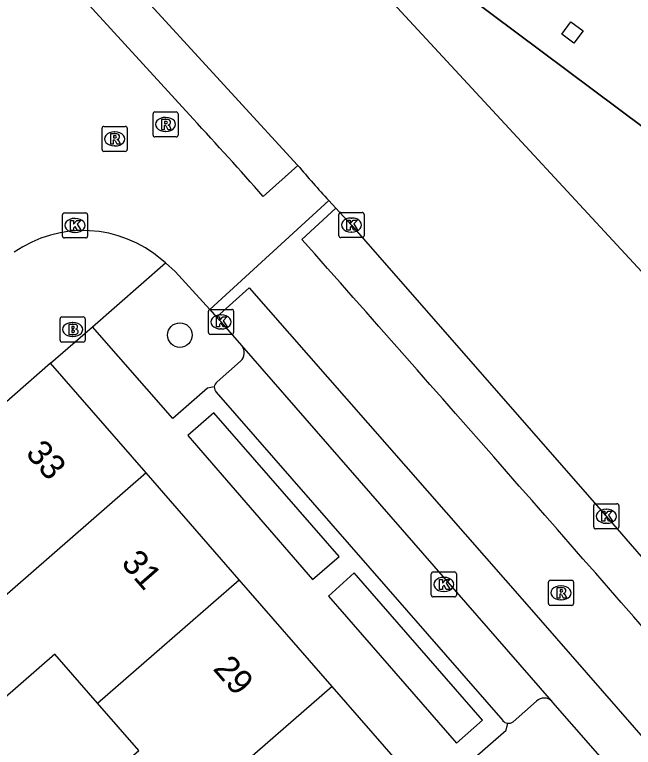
# Model space of a CAD drawing. Extents: x 159718 to 160783, y 383290 to 384030.
# Drawn here: x 160469.71 to 160494.4, y 383567.02 to 383596.25 of the extents above; entities that cross this region are included whole.
import ezdxf

# ---------------------------------------------------------------- set-up
doc = ezdxf.new("R2010")
doc.units = 0
for name, color, linetype in [('IMGEO_Boom', 7, 'Continuous'), ('IMGEO_Brandkraan', 7, 'Continuous'), ('IMGEO_Kolk', 7, 'Continuous'), ('IMGEO_Pand', 7, 'Continuous'), ('IMGEO_Pand_nummerreeks', 7, 'Continuous'), ('IMGEO_Pand_overbouw', 7, 'Continuous'), ('IMGEO_Parkeervlak_open', 7, 'Continuous'), ('IMGEO_Rijbaan_lokaal_gesloten', 7, 'Continuous'), ('IMGEO_Rijbaan_lokaal_open', 7, 'Continuous'), ('IMGEO_Rioolput', 7, 'Continuous'), ('IMGEO_Voetpad_open', 7, 'Continuous')]:
    doc.layers.add(name, color=color, linetype=linetype)

msp = doc.modelspace()

# ---------------------------------------------------------------- linework, layer by layer
at = {"layer": 'IMGEO_Boom'}
msp.add_circle((160476.304, 383583.468), 0.489, dxfattribs=at)
at = {"layer": 'IMGEO_Brandkraan'}
for p, q in [((160471.525, 383583.266), (160471.525, 383584.118)), ((160471.6, 383584.192), (160472.452, 383584.192)), ((160472.526, 383584.118), (160472.526, 383583.266)), ((160472.013, 383583.972), (160472.038, 383583.972)), ((160472.452, 383583.192), (160471.6, 383583.192)), ((160472.036, 383583.412), (160472.011, 383583.412))]:
    msp.add_line(p, q, dxfattribs=at)
for points in [[(160471.525, 383583.266), (160471.525, 383584.118)], [(160471.6, 383584.192), (160472.452, 383584.192)], [(160472.526, 383584.118), (160472.526, 383583.266)], [(160471.873, 383583.892), (160471.873, 383583.492), (160472.086, 383583.492)], [(160472.104, 383583.892), (160471.873, 383583.892)], [(160472.052, 383583.811), (160471.998, 383583.811), (160471.998, 383583.735)], [(160471.998, 383583.735), (160472.051, 383583.735)], [(160472.06, 383583.659), (160471.998, 383583.659), (160471.998, 383583.578)], [(160471.998, 383583.578), (160472.06, 383583.578)], [(160472.452, 383583.192), (160471.6, 383583.192)]]:
    msp.add_lwpolyline(points, dxfattribs=at)
for centre, radius, start, end in [((160471.602, 383584.116), 0.0765, 91.552, 178.448), ((160471.602, 383584.116), 0.0765, 91.552, 178.448), ((160472.45, 383584.116), 0.0765, 1.552, 88.448), ((160472.45, 383584.116), 0.0765, 1.552, 88.448), ((160472.053, 383583.773), 0.0379, 267.8285, 90.9355), ((160472.108, 383583.747), 0.145, 59.4692, 91.5367), ((160472.133, 383583.794), 0.0922, 285.5137, 58.1501), ((160472.061, 383583.618), 0.0404, 269.8759, 90.5077), ((160472.092, 383583.743), 0.251, 268.6676, 293.5347), ((160472.138, 383583.602), 0.105, 301.3115, 78.989), ((160471.602, 383583.268), 0.0765, 181.552, 268.448), ((160471.602, 383583.268), 0.0765, 181.552, 268.448), ((160472.45, 383583.268), 0.0765, 271.552, 358.448), ((160472.45, 383583.268), 0.0765, 271.552, 358.448)]:
    msp.add_arc(centre, radius, start, end, dxfattribs=at)
for centre, major_axis, ratio, start_param, end_param in [((160472.012, 383583.692), (-0.387, 0.002), 0.722429, 4.712389, 7.853982), ((160472.037, 383583.692), (-0.39, 0.002), 0.717154, 1.570796, 4.712389)]:
    msp.add_ellipse(centre, major_axis=major_axis, ratio=ratio, start_param=start_param, end_param=end_param, dxfattribs=at)
at = {"layer": 'IMGEO_Kolk'}
for p, q in [((160471.622, 383587.416), (160471.622, 383588.268)), ((160471.697, 383588.342), (160472.549, 383588.342)), ((160472.623, 383588.268), (160472.623, 383587.416)), ((160482.65, 383587.432), (160482.65, 383588.284)), ((160482.725, 383588.358), (160483.577, 383588.358)), ((160483.651, 383588.284), (160483.651, 383587.432)), ((160472.11, 383588.122), (160472.135, 383588.122)), ((160483.138, 383588.138), (160483.163, 383588.138)), ((160472.133, 383587.562), (160472.108, 383587.562)), ((160483.161, 383587.578), (160483.136, 383587.578)), ((160472.549, 383587.342), (160471.697, 383587.342)), ((160483.577, 383587.358), (160482.725, 383587.358)), ((160477.446, 383583.568), (160477.446, 383584.42)), ((160477.521, 383584.494), (160478.373, 383584.494)), ((160478.447, 383584.42), (160478.447, 383583.568)), ((160477.934, 383584.274), (160477.959, 383584.274)), ((160478.373, 383583.494), (160477.521, 383583.494)), ((160477.957, 383583.714), (160477.932, 383583.714)), ((160492.817, 383575.815), (160492.817, 383576.667)), ((160492.892, 383576.741), (160493.744, 383576.741)), ((160493.305, 383576.521), (160493.33, 383576.521)), ((160493.818, 383576.667), (160493.818, 383575.815)), ((160493.328, 383575.961), (160493.303, 383575.961)), ((160493.744, 383575.741), (160492.892, 383575.741)), ((160486.337, 383573.098), (160486.337, 383573.95)), ((160486.412, 383574.024), (160487.264, 383574.024)), ((160487.338, 383573.95), (160487.338, 383573.098)), ((160486.825, 383573.804), (160486.85, 383573.804)), ((160486.848, 383573.244), (160486.823, 383573.244)), ((160487.264, 383573.024), (160486.412, 383573.024))]:
    msp.add_line(p, q, dxfattribs=at)
for points in [[(160471.622, 383587.416), (160471.622, 383588.268)], [(160471.697, 383588.342), (160472.549, 383588.342)], [(160472.623, 383588.268), (160472.623, 383587.416)], [(160482.65, 383587.432), (160482.65, 383588.284)], [(160482.725, 383588.358), (160483.577, 383588.358)], [(160483.651, 383588.284), (160483.651, 383587.432)], [(160471.943, 383588.042), (160472.066, 383588.042), (160472.066, 383587.891), (160472.196, 383588.042), (160472.36, 383588.042), (160472.214, 383587.891), (160472.367, 383587.642), (160472.215, 383587.642), (160472.13, 383587.806), (160472.066, 383587.739), (160472.066, 383587.642), (160471.943, 383587.642), (160471.943, 383588.042)], [(160482.971, 383588.058), (160483.094, 383588.058), (160483.094, 383587.907), (160483.224, 383588.058), (160483.388, 383588.058), (160483.242, 383587.907), (160483.395, 383587.658), (160483.243, 383587.658), (160483.158, 383587.822), (160483.094, 383587.755), (160483.094, 383587.658), (160482.971, 383587.658), (160482.971, 383588.058)], [(160472.549, 383587.342), (160471.697, 383587.342)], [(160483.577, 383587.358), (160482.725, 383587.358)], [(160477.446, 383583.568), (160477.446, 383584.42)], [(160477.521, 383584.494), (160478.373, 383584.494)], [(160478.447, 383584.42), (160478.447, 383583.568)], [(160477.767, 383584.194), (160477.89, 383584.194), (160477.89, 383584.043), (160478.02, 383584.194), (160478.184, 383584.194), (160478.038, 383584.043), (160478.191, 383583.794), (160478.039, 383583.794), (160477.954, 383583.958), (160477.89, 383583.891), (160477.89, 383583.794), (160477.767, 383583.794), (160477.767, 383584.194)], [(160478.373, 383583.494), (160477.521, 383583.494)], [(160492.817, 383575.815), (160492.817, 383576.667)], [(160492.892, 383576.741), (160493.744, 383576.741)], [(160493.818, 383576.667), (160493.818, 383575.815)], [(160493.138, 383576.441), (160493.261, 383576.441), (160493.261, 383576.29), (160493.391, 383576.441), (160493.555, 383576.441), (160493.409, 383576.29), (160493.562, 383576.041), (160493.41, 383576.041), (160493.325, 383576.205), (160493.261, 383576.138), (160493.261, 383576.041), (160493.138, 383576.041), (160493.138, 383576.441)], [(160493.744, 383575.741), (160492.892, 383575.741)], [(160486.337, 383573.098), (160486.337, 383573.95)], [(160486.412, 383574.024), (160487.264, 383574.024)], [(160487.338, 383573.95), (160487.338, 383573.098)], [(160486.658, 383573.724), (160486.781, 383573.724), (160486.781, 383573.573), (160486.911, 383573.724), (160487.075, 383573.724), (160486.929, 383573.573), (160487.082, 383573.324), (160486.93, 383573.324), (160486.845, 383573.488), (160486.781, 383573.421), (160486.781, 383573.324), (160486.658, 383573.324), (160486.658, 383573.724)], [(160487.264, 383573.024), (160486.412, 383573.024)]]:
    msp.add_lwpolyline(points, dxfattribs=at)
for centre, start, end in [((160471.699, 383588.266), 91.552, 178.448), ((160471.699, 383588.266), 91.552, 178.448), ((160472.547, 383588.266), 1.552, 88.448), ((160472.547, 383588.266), 1.552, 88.448), ((160482.727, 383588.282), 91.552, 178.448), ((160482.727, 383588.282), 91.552, 178.448), ((160483.575, 383588.282), 1.552, 88.448), ((160483.575, 383588.282), 1.552, 88.448), ((160471.699, 383587.418), 181.552, 268.448), ((160471.699, 383587.418), 181.552, 268.448), ((160472.547, 383587.418), 271.552, 358.448), ((160472.547, 383587.418), 271.552, 358.448), ((160482.727, 383587.434), 181.552, 268.448), ((160482.727, 383587.434), 181.552, 268.448), ((160483.575, 383587.434), 271.552, 358.448), ((160483.575, 383587.434), 271.552, 358.448), ((160477.523, 383584.418), 91.552, 178.448), ((160477.523, 383584.418), 91.552, 178.448), ((160478.371, 383584.418), 1.552, 88.448), ((160478.371, 383584.418), 1.552, 88.448), ((160477.523, 383583.57), 181.552, 268.448), ((160477.523, 383583.57), 181.552, 268.448), ((160478.371, 383583.57), 271.552, 358.448), ((160478.371, 383583.57), 271.552, 358.448), ((160492.894, 383576.665), 91.552, 178.448), ((160492.894, 383576.665), 91.552, 178.448), ((160493.742, 383576.665), 1.552, 88.448), ((160493.742, 383576.665), 1.552, 88.448), ((160492.894, 383575.817), 181.552, 268.448), ((160492.894, 383575.817), 181.552, 268.448), ((160493.742, 383575.817), 271.552, 358.448), ((160493.742, 383575.817), 271.552, 358.448), ((160486.414, 383573.948), 91.552, 178.448), ((160486.414, 383573.948), 91.552, 178.448), ((160487.262, 383573.948), 1.552, 88.448), ((160487.262, 383573.948), 1.552, 88.448), ((160486.414, 383573.1), 181.552, 268.448), ((160486.414, 383573.1), 181.552, 268.448), ((160487.262, 383573.1), 271.552, 358.448), ((160487.262, 383573.1), 271.552, 358.448)]:
    msp.add_arc(centre, 0.0765, start, end, dxfattribs=at)
for centre, major_axis, ratio, start_param, end_param in [((160472.109, 383587.842), (-0.387, 0.002), 0.722429, 4.712389, 7.853982), ((160472.134, 383587.842), (-0.39, 0.002), 0.717154, 1.570796, 4.712389), ((160483.137, 383587.858), (-0.387, 0.002), 0.722429, 4.712389, 7.853982), ((160483.162, 383587.858), (-0.39, 0.002), 0.717154, 1.570796, 4.712389), ((160477.933, 383583.994), (-0.387, 0.002), 0.722429, 4.712389, 7.853982), ((160477.958, 383583.994), (-0.39, 0.002), 0.717154, 1.570796, 4.712389), ((160493.304, 383576.241), (-0.387, 0.002), 0.722429, 4.712389, 7.853982), ((160493.329, 383576.241), (-0.39, 0.002), 0.717154, 1.570796, 4.712389), ((160486.824, 383573.524), (-0.387, 0.002), 0.722429, 4.712389, 7.853982), ((160486.849, 383573.524), (-0.39, 0.002), 0.717154, 1.570796, 4.712389)]:
    msp.add_ellipse(centre, major_axis=major_axis, ratio=ratio, start_param=start_param, end_param=end_param, dxfattribs=at)
at = {"layer": 'IMGEO_Pand'}
for points in [[(160492.027, 383595.119), (160491.545, 383595.478), (160491.906, 383595.962), (160492.388, 383595.603), (160492.027, 383595.119)], [(160471.15, 383582.344), (160465.436, 383577.354)], [(160474.958, 383577.974), (160471.15, 383582.344)], [(160474.958, 383577.974), (160464.383, 383568.766)], [(160478.672, 383573.711), (160474.958, 383577.974)], [(160473.02, 383568.79), (160478.672, 383573.711)], [(160482.386, 383569.449), (160478.672, 383573.711)], [(160473.02, 383568.79), (160471.319, 383570.744), (160466.394, 383566.457), (160465.817, 383567.119), (160464.383, 383568.766)], [(160482.386, 383569.449), (160471.801, 383560.232)], [(160486.1, 383565.186), (160482.386, 383569.449)], [(160471.801, 383560.232), (160469.735, 383562.605), (160474.667, 383566.899), (160473.02, 383568.79)]]:
    msp.add_lwpolyline(points, dxfattribs=at)
at = {"layer": 'IMGEO_Pand_overbouw'}
msp.add_lwpolyline([(160495.917, 383597.511), (160494.524, 383597.305), (160494.162, 383596.825), (160485.454, 383603.334), (160487.673, 383606.423), (160484.166, 383609.039), (160482.89, 383607.324), (160483.214, 383605.19), (160484.788, 383603.997), (160482.562, 383600.899), (160499.95, 383587.91), (160506.865, 383582.745), (160509.059, 383585.69), (160505.713, 383588.193), (160502.755, 383590.402), (160499.96, 383592.491), (160499.769, 383592.634), (160500.15, 383593.098), (160500, 383594.241), (160499.967, 383594.493)], close=True, dxfattribs=at)
at = {"layer": 'IMGEO_Parkeervlak_open'}
for points in [[(160478.73, 383582.425), (160477.792, 383581.6)], [(160489.596, 383568.037), (160490.539, 383568.866)]]:
    msp.add_lwpolyline(points, dxfattribs=at)
for centre, radius, start, end in [((160478.408, 383582.761), 0.465, 313.8084, 38.3076), ((160477.945, 383581.38), 0.268, 124.9117, 175.9676), ((160490.84, 383568.571), 0.421, 43.8069, 135.6249), ((160489.422, 383568.291), 0.308, 263.3212, 304.4943)]:
    msp.add_arc(centre, radius, start, end, dxfattribs=at)
at = {"layer": 'IMGEO_Rijbaan_lokaal_gesloten'}
for points in [[(160465.403, 383607.286), (160464.052, 383606.061), (160476.835, 383592.097)], [(160465.403, 383607.286), (160472.595, 383599.429), (160473.686, 383598.238), (160480.986, 383590.263), (160481.009, 383590.237)], [(160479.625, 383588.999), (160481.009, 383590.237)], [(160481.177, 383587.285), (160482.526, 383588.525)], [(160482.526, 383588.525), (160483.151, 383587.858), (160493.318, 383576.241), (160507.09, 383560.37), (160517.403, 383548.451), (160520.715, 383544.684), (160521.52, 383543.759), (160535.801, 383527.329), (160536.623, 383526.415), (160539.338, 383523.165), (160540.32, 383521.963), (160544.286, 383517.022), (160545.265, 383515.781), (160546.841, 383513.764), (160554.904, 383502.868), (160555.82, 383501.543), (160555.982, 383501.307), (160556.128, 383501.1)], [(160477.772, 383584.186), (160479.071, 383585.36), (160490.051, 383572.83), (160501.265, 383559.983), (160524.739, 383532.986), (160523.405, 383531.808)], [(160478.773, 383583.049), (160477.947, 383583.994), (160477.772, 383584.186)], [(160491.144, 383568.863), (160478.773, 383583.049)], [(160493.877, 383565.712), (160493.826, 383565.795), (160491.187, 383568.81), (160491.144, 383568.863)]]:
    msp.add_lwpolyline(points, dxfattribs=at)
for centre, radius, start, end in [((160354.196, 383478.846), 166.931, 41.29009, 42.7211), ((158291.054, 381648.545), 2924.953, 41.032441, 41.515876)]:
    msp.add_arc(centre, radius, start, end, dxfattribs=at)
at = {"layer": 'IMGEO_Rijbaan_lokaal_open'}
for points in [[(160506.865, 383582.745), (160499.95, 383587.91), (160482.562, 383600.899), (160484.788, 383603.997), (160483.214, 383605.19), (160482.89, 383607.324), (160484.166, 383609.039)], [(160481.663, 383600.119), (160500.034, 383580.268), (160503.013, 383576.856), (160502.786, 383576.666), (160504.559, 383574.613), (160504.469, 383574.53), (160505.419, 383573.386), (160505.313, 383573.28), (160506.11, 383572.358), (160505.892, 383572.187), (160507.269, 383570.583), (160507.15, 383570.491), (160507.725, 383569.807), (160507.406, 383569.519), (160507.804, 383569.072), (160507.126, 383568.466), (160507.308, 383568.232), (160507.099, 383568.061), (160508.276, 383566.695), (160508.753, 383566.325), (160511.866, 383562.752)], [(160482.245, 383588.832), (160477.499, 383584.485)], [(160482.526, 383588.525), (160482.245, 383588.832)], [(160475.727, 383586.349), (160475.591, 383586.469)], [(160477.499, 383584.485), (160476.119, 383586.001), (160475.727, 383586.349)], [(160477.499, 383584.485), (160477.772, 383584.186)]]:
    msp.add_lwpolyline(points, dxfattribs=at)
for centre, radius, start, end in [((160523.618, 383626.475), 55.935, 220.3801, 222.297), ((160472.446, 383582.832), 4.808, 49.1527, 124.9472)]:
    msp.add_arc(centre, radius, start, end, dxfattribs=at)
at = {"layer": 'IMGEO_Rioolput'}
for p, q in [((160475.234, 383591.445), (160475.234, 383592.297)), ((160475.309, 383592.371), (160476.161, 383592.371)), ((160476.235, 383592.297), (160476.235, 383591.445)), ((160475.722, 383592.151), (160475.747, 383592.151)), ((160473.201, 383590.868), (160473.201, 383591.72)), ((160473.276, 383591.794), (160474.128, 383591.794)), ((160474.202, 383591.72), (160474.202, 383590.868)), ((160473.689, 383591.574), (160473.714, 383591.574)), ((160476.161, 383591.371), (160475.309, 383591.371)), ((160475.745, 383591.591), (160475.72, 383591.591)), ((160474.128, 383590.794), (160473.276, 383590.794)), ((160473.712, 383591.014), (160473.687, 383591.014)), ((160491.01, 383572.761), (160491.01, 383573.613)), ((160491.085, 383573.687), (160491.937, 383573.687)), ((160492.011, 383573.613), (160492.011, 383572.761)), ((160491.498, 383573.467), (160491.523, 383573.467)), ((160491.937, 383572.687), (160491.085, 383572.687)), ((160491.521, 383572.907), (160491.496, 383572.907))]:
    msp.add_line(p, q, dxfattribs=at)
for points in [[(160475.234, 383591.445), (160475.234, 383592.297)], [(160475.309, 383592.371), (160476.161, 383592.371)], [(160476.235, 383592.297), (160476.235, 383591.445)], [(160475.823, 383592.069), (160475.571, 383592.071), (160475.571, 383591.671)], [(160475.749, 383591.99), (160475.695, 383591.99), (160475.695, 383591.909)], [(160473.201, 383590.868), (160473.201, 383591.72)], [(160473.276, 383591.794), (160474.128, 383591.794)], [(160474.202, 383591.72), (160474.202, 383590.868)], [(160475.571, 383591.671), (160475.695, 383591.671), (160475.695, 383591.833), (160475.706, 383591.833)], [(160475.695, 383591.909), (160475.747, 383591.909)], [(160475.753, 383591.804), (160475.824, 383591.671), (160475.964, 383591.671), (160475.899, 383591.797)], [(160473.79, 383591.492), (160473.538, 383591.494), (160473.538, 383591.094)], [(160473.716, 383591.413), (160473.662, 383591.413), (160473.662, 383591.332)], [(160476.161, 383591.371), (160475.309, 383591.371)], [(160473.538, 383591.094), (160473.662, 383591.094), (160473.662, 383591.256), (160473.673, 383591.256)], [(160473.662, 383591.332), (160473.714, 383591.332)], [(160473.72, 383591.227), (160473.791, 383591.094), (160473.931, 383591.094), (160473.866, 383591.22)], [(160474.128, 383590.794), (160473.276, 383590.794)], [(160491.01, 383572.761), (160491.01, 383573.613)], [(160491.085, 383573.687), (160491.937, 383573.687)], [(160492.011, 383573.613), (160492.011, 383572.761)], [(160491.599, 383573.385), (160491.347, 383573.387), (160491.347, 383572.987)], [(160491.525, 383573.306), (160491.471, 383573.306), (160491.471, 383573.225)], [(160491.347, 383572.987), (160491.471, 383572.987), (160491.471, 383573.149), (160491.482, 383573.149)], [(160491.471, 383573.225), (160491.523, 383573.225)], [(160491.529, 383573.12), (160491.6, 383572.987), (160491.74, 383572.987), (160491.675, 383573.113)], [(160491.937, 383572.687), (160491.085, 383572.687)]]:
    msp.add_lwpolyline(points, dxfattribs=at)
for centre, radius, start, end in [((160475.311, 383592.295), 0.0765, 91.552, 178.448), ((160475.311, 383592.295), 0.0765, 91.552, 178.448), ((160476.159, 383592.295), 0.0765, 1.552, 88.448), ((160476.159, 383592.295), 0.0765, 1.552, 88.448), ((160475.755, 383591.894), 0.0964, 77.0061, 93.1865), ((160475.769, 383591.951), 0.0378, 276.6634, 79.6772), ((160475.822, 383591.959), 0.109, 350.3612, 89.416), ((160473.278, 383591.718), 0.0765, 91.552, 178.448), ((160473.278, 383591.718), 0.0765, 91.552, 178.448), ((160474.126, 383591.718), 0.0765, 1.552, 88.448), ((160474.126, 383591.718), 0.0765, 1.552, 88.448), ((160475.705, 383591.78), 0.0533, 26.0293, 88.6989), ((160475.731, 383592.098), 0.19, 274.7715, 282.9687), ((160475.82, 383591.959), 0.112, 277.5842, 350.9817), ((160475.804, 383591.744), 0.108, 29.5134, 73.7905), ((160473.722, 383591.317), 0.0964, 77.0061, 93.1865), ((160473.736, 383591.374), 0.0378, 276.6634, 79.6772), ((160473.789, 383591.382), 0.109, 350.3612, 89.416), ((160473.787, 383591.382), 0.112, 277.5842, 350.9817), ((160475.311, 383591.447), 0.0765, 181.552, 268.448), ((160475.311, 383591.447), 0.0765, 181.552, 268.448), ((160476.159, 383591.447), 0.0765, 271.552, 358.448), ((160476.159, 383591.447), 0.0765, 271.552, 358.448), ((160473.672, 383591.203), 0.0533, 26.0293, 88.6989), ((160473.698, 383591.521), 0.19, 274.7715, 282.9687), ((160473.771, 383591.167), 0.108, 29.5134, 73.7905), ((160473.278, 383590.87), 0.0765, 181.552, 268.448), ((160473.278, 383590.87), 0.0765, 181.552, 268.448), ((160474.126, 383590.87), 0.0765, 271.552, 358.448), ((160474.126, 383590.87), 0.0765, 271.552, 358.448), ((160491.087, 383573.611), 0.0765, 91.552, 178.448), ((160491.087, 383573.611), 0.0765, 91.552, 178.448), ((160491.935, 383573.611), 0.0765, 1.552, 88.448), ((160491.935, 383573.611), 0.0765, 1.552, 88.448), ((160491.531, 383573.21), 0.0964, 77.0061, 93.1865), ((160491.545, 383573.267), 0.0378, 276.6634, 79.6772), ((160491.598, 383573.275), 0.109, 350.3612, 89.416), ((160491.596, 383573.275), 0.112, 277.5842, 350.9817), ((160491.481, 383573.096), 0.0533, 26.0293, 88.6989), ((160491.507, 383573.414), 0.19, 274.7715, 282.9687), ((160491.58, 383573.06), 0.108, 29.5134, 73.7905), ((160491.087, 383572.763), 0.0765, 181.552, 268.448), ((160491.087, 383572.763), 0.0765, 181.552, 268.448), ((160491.935, 383572.763), 0.0765, 271.552, 358.448), ((160491.935, 383572.763), 0.0765, 271.552, 358.448)]:
    msp.add_arc(centre, radius, start, end, dxfattribs=at)
for centre, major_axis, ratio, start_param, end_param in [((160475.721, 383591.871), (-0.387, 0.002), 0.722429, 4.712389, 7.853982), ((160475.746, 383591.871), (-0.39, 0.002), 0.717154, 1.570796, 4.712389), ((160473.688, 383591.294), (-0.387, 0.002), 0.722429, 4.712389, 7.853982), ((160473.713, 383591.294), (-0.39, 0.002), 0.717154, 1.570796, 4.712389), ((160491.497, 383573.187), (-0.387, 0.002), 0.722429, 4.712389, 7.853982), ((160491.522, 383573.187), (-0.39, 0.002), 0.717154, 1.570796, 4.712389)]:
    msp.add_ellipse(centre, major_axis=major_axis, ratio=ratio, start_param=start_param, end_param=end_param, dxfattribs=at)
at = {"layer": 'IMGEO_Voetpad_open'}
for points in [[(160472.825, 383583.793), (160475.727, 383586.349)], [(160471.15, 383582.344), (160472.825, 383583.793)], [(160477.678, 383581.399), (160477.406, 383581.356), (160476.019, 383580.147), (160472.825, 383583.793)], [(160477.758, 383581.188), (160489.183, 383568.1)], [(160476.628, 383579.465), (160481.595, 383573.719), (160482.659, 383574.637), (160477.655, 383580.374), (160476.628, 383579.465)], [(160482.229, 383573.06), (160487.342, 383567.186), (160488.375, 383568.108), (160483.258, 383573.98), (160482.229, 383573.06)], [(160492.736, 383564.176), (160492.441, 383564.08), (160491.13, 383563.008), (160487.962, 383566.522), (160489.316, 383567.715), (160489.386, 383567.985)]]:
    msp.add_lwpolyline(points, dxfattribs=at)
for centre, radius, start, end in [((160477.949, 383581.381), 0.272, 176.2426, 225.2856), ((160489.421, 383568.284), 0.301, 217.6841, 263.2525)]:
    msp.add_arc(centre, radius, start, end, dxfattribs=at)

# ---------------------------------------------------------------- texts
at = {"layer": 'IMGEO_Pand_nummerreeks'}
for s, p in [('33', (160470.115, 383578.734)), ('31', (160473.929, 383574.354)), ('29', (160477.592, 383570.145))]:
    msp.add_text(s, height=1, rotation=311.0465, dxfattribs=at).set_placement(p)

doc.saveas('drawing.dxf')
